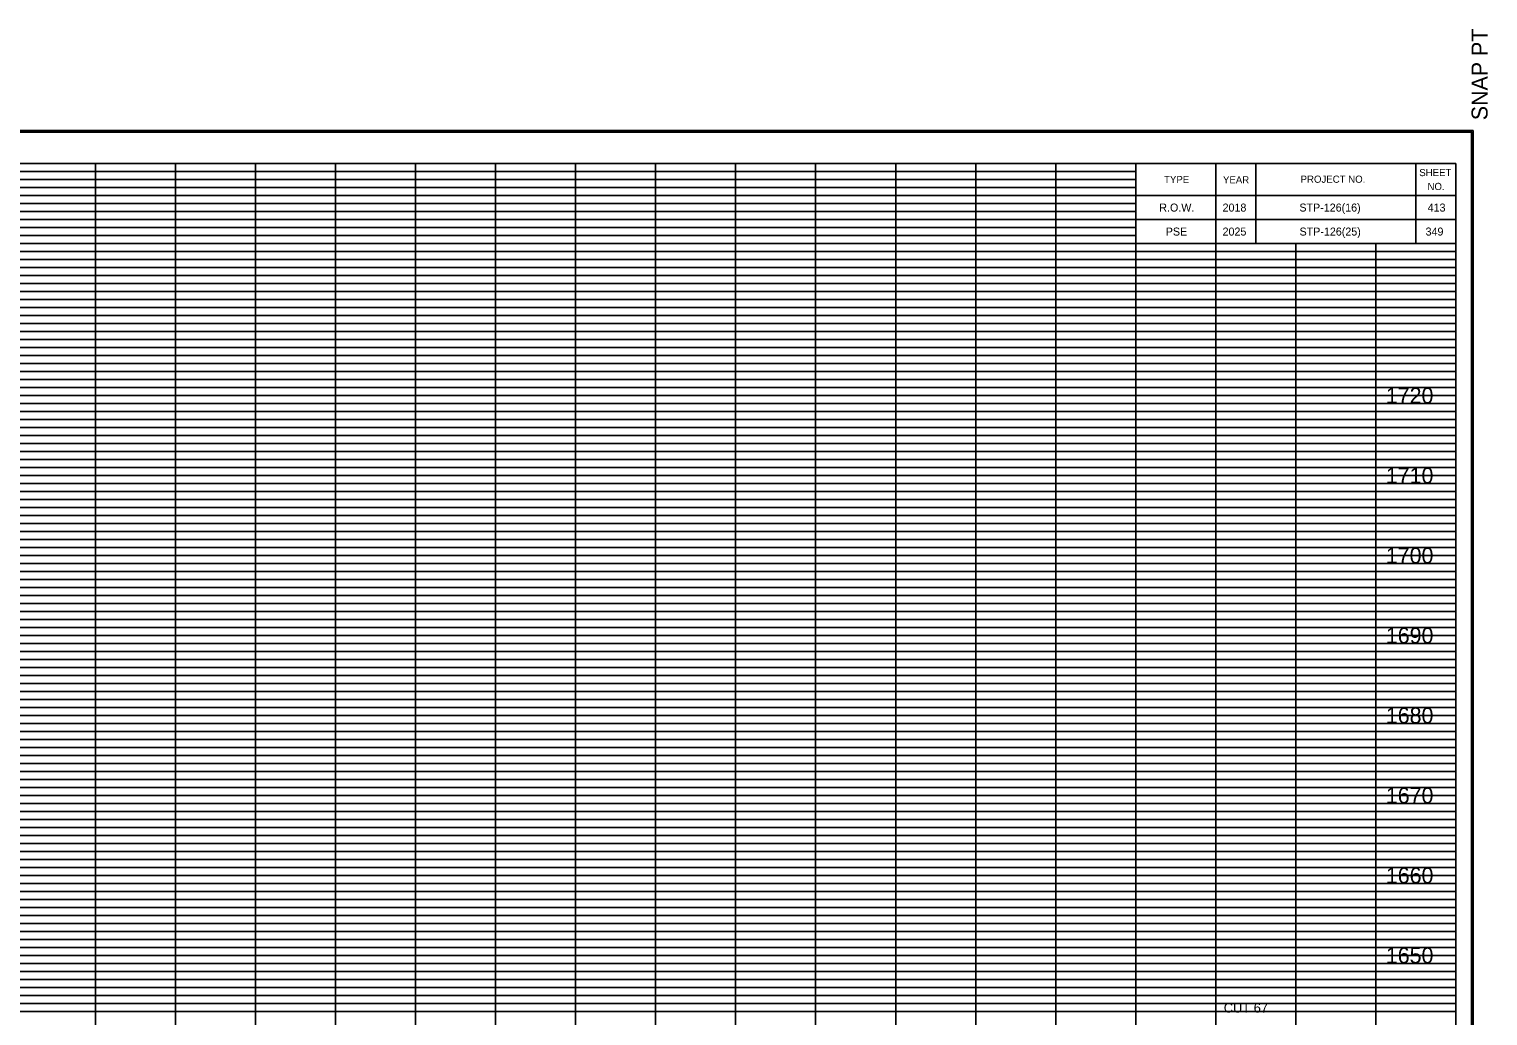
# Model space of a CAD drawing. Extents: x 980 to 1324, y 978 to 1497.
# Drawn here: x 1141.7 to 1324, y 1103.4 to 1226.8 of the extents above; entities that cross this region are included whole.
import ezdxf

# ---------------------------------------------------------------- set-up
doc = ezdxf.new("R2010")
doc.units = 0
for name, color, linetype in [('DESIGN - SCRATCH - User 1', 7, 'Continuous'), ('DESIGN - SHEET - Corner Text', 7, 'Continuous'), ('DESIGN - SHEET - Light Grid', 7, 'Continuous'), ('DESIGN - SHEET - Linework', 7, 'Continuous'), ('DESIGN - SHEET - Plot Shape', 7, 'Continuous'), ('DESIGN - TYPICAL - Finished Grade and Subgrade', 7, 'Continuous'), ('DESIGN - TYPICAL - Text', 7, 'Continuous')]:
    doc.layers.add(name, color=color, linetype=linetype)

# ---------------------------------------------------------------- blocks, each defined once
blk = doc.blocks.new('XSTSHT')
at = {"layer": 'DESIGN - SCRATCH - User 1'}
for p, q in [((28.5, 20.45), (28.5, 20.45)), ((29.24, 20.45), (29.24, 20.45)), ((30.49, 20.45), (30.49, 20.45)), ((31.74, 20.45), (31.74, 20.45)), ((28.5, 20.15), (28.5, 20.15)), ((29.24, 20.15), (29.24, 20.15)), ((30.49, 20.15), (30.49, 20.15)), ((31.74, 20.15), (31.74, 20.15))]:
    blk.add_line(p, q, dxfattribs=at)
at = {"layer": 'DESIGN - SHEET - Light Grid'}
for p, q in [((8, 20.9), (16, 20.9)), ((8, 20.8), (16, 20.8)), ((16, 20.9), (24, 20.9)), ((16, 20.8), (24, 20.8)), ((24, 20.9), (28, 20.9)), ((24, 20.8), (28, 20.8)), ((8, 20.7), (16, 20.7)), ((8, 20.6), (16, 20.6)), ((16, 20.7), (24, 20.7)), ((16, 20.6), (24, 20.6)), ((24, 20.7), (28, 20.7)), ((24, 20.6), (28, 20.6)), ((8, 20.5), (16, 20.5)), ((16, 20.5), (24, 20.5)), ((24, 20.5), (28, 20.5)), ((8, 20.4), (16, 20.4)), ((8, 20.3), (16, 20.3)), ((16, 20.4), (24, 20.4)), ((16, 20.3), (24, 20.3)), ((24, 20.4), (28, 20.4)), ((24, 20.3), (28, 20.3)), ((8, 20.2), (16, 20.2)), ((8, 20.1), (16, 20.1)), ((16, 20.2), (24, 20.2)), ((16, 20.1), (24, 20.1)), ((24, 20.2), (28, 20.2)), ((24, 20.1), (28, 20.1)), ((8, 19.9), (16, 19.9)), ((16, 19.9), (24, 19.9)), ((24, 19.9), (32, 19.9)), ((8, 19.8), (16, 19.8)), ((8, 19.7), (16, 19.7)), ((16, 19.8), (24, 19.8)), ((16, 19.7), (24, 19.7)), ((24, 19.8), (32, 19.8)), ((24, 19.7), (32, 19.7)), ((8, 19.6), (16, 19.6)), ((16, 19.6), (24, 19.6)), ((24, 19.6), (32, 19.6)), ((8, 19.5), (16, 19.5)), ((8, 19.4), (16, 19.4)), ((16, 19.5), (24, 19.5)), ((16, 19.4), (24, 19.4)), ((24, 19.5), (32, 19.5)), ((24, 19.4), (32, 19.4)), ((8, 19.3), (16, 19.3)), ((8, 19.2), (16, 19.2)), ((16, 19.3), (24, 19.3)), ((16, 19.2), (24, 19.2)), ((24, 19.3), (32, 19.3)), ((24, 19.2), (32, 19.2)), ((8, 19.1), (16, 19.1)), ((16, 19.1), (24, 19.1)), ((24, 19.1), (32, 19.1)), ((8, 18.9), (16, 18.9)), ((8, 18.8), (16, 18.8)), ((16, 18.9), (24, 18.9)), ((16, 18.8), (24, 18.8)), ((24, 18.9), (32, 18.9)), ((24, 18.8), (32, 18.8)), ((8, 18.7), (16, 18.7)), ((8, 18.6), (16, 18.6)), ((16, 18.7), (24, 18.7)), ((16, 18.6), (24, 18.6)), ((24, 18.7), (32, 18.7)), ((24, 18.6), (32, 18.6)), ((8, 18.5), (16, 18.5)), ((16, 18.5), (24, 18.5)), ((24, 18.5), (32, 18.5)), ((8, 18.4), (16, 18.4)), ((8, 18.3), (16, 18.3)), ((16, 18.4), (24, 18.4)), ((16, 18.3), (24, 18.3)), ((24, 18.4), (32, 18.4)), ((24, 18.3), (32, 18.3)), ((8, 18.2), (16, 18.2)), ((8, 18.1), (16, 18.1)), ((16, 18.2), (24, 18.2)), ((16, 18.1), (24, 18.1)), ((24, 18.2), (32, 18.2)), ((24, 18.1), (32, 18.1)), ((8, 17.9), (16, 17.9)), ((16, 17.9), (24, 17.9)), ((24, 17.9), (32, 17.9)), ((8, 17.8), (16, 17.8)), ((8, 17.7), (16, 17.7)), ((16, 17.8), (24, 17.8)), ((16, 17.7), (24, 17.7)), ((24, 17.8), (32, 17.8)), ((24, 17.7), (32, 17.7)), ((8, 17.6), (16, 17.6)), ((8, 17.5), (16, 17.5)), ((16, 17.6), (24, 17.6)), ((16, 17.5), (24, 17.5)), ((24, 17.6), (32, 17.6)), ((24, 17.5), (32, 17.5)), ((8, 17.4), (16, 17.4)), ((16, 17.4), (24, 17.4)), ((24, 17.4), (32, 17.4)), ((8, 17.3), (16, 17.3)), ((8, 17.2), (16, 17.2)), ((16, 17.3), (24, 17.3)), ((16, 17.2), (24, 17.2)), ((24, 17.3), (32, 17.3)), ((24, 17.2), (32, 17.2)), ((8, 17.1), (16, 17.1)), ((16, 17.1), (24, 17.1)), ((24, 17.1), (32, 17.1)), ((8, 16.9), (16, 16.9)), ((8, 16.8), (16, 16.8)), ((16, 16.9), (24, 16.9)), ((16, 16.8), (24, 16.8)), ((24, 16.9), (32, 16.9)), ((24, 16.8), (32, 16.8)), ((8, 16.7), (16, 16.7)), ((8, 16.6), (16, 16.6)), ((16, 16.7), (24, 16.7)), ((16, 16.6), (24, 16.6)), ((24, 16.7), (32, 16.7)), ((24, 16.6), (32, 16.6)), ((8, 16.5), (16, 16.5)), ((16, 16.5), (24, 16.5)), ((24, 16.5), (32, 16.5)), ((8, 16.4), (16, 16.4)), ((8, 16.3), (16, 16.3)), ((16, 16.4), (24, 16.4)), ((16, 16.3), (24, 16.3)), ((24, 16.4), (32, 16.4)), ((24, 16.3), (32, 16.3)), ((8, 16.2), (16, 16.2)), ((8, 16.1), (16, 16.1)), ((16, 16.2), (24, 16.2)), ((16, 16.1), (24, 16.1)), ((24, 16.2), (32, 16.2)), ((24, 16.1), (32, 16.1)), ((8, 15.9), (16, 15.9)), ((16, 15.9), (24, 15.9)), ((24, 15.9), (32, 15.9)), ((8, 15.8), (16, 15.8)), ((8, 15.7), (16, 15.7)), ((16, 15.8), (24, 15.8)), ((16, 15.7), (24, 15.7)), ((24, 15.8), (32, 15.8)), ((24, 15.7), (32, 15.7)), ((8, 15.6), (16, 15.6)), ((8, 15.5), (16, 15.5)), ((16, 15.6), (24, 15.6)), ((16, 15.5), (24, 15.5)), ((24, 15.6), (32, 15.6)), ((24, 15.5), (32, 15.5)), ((8, 15.4), (16, 15.4)), ((16, 15.4), (24, 15.4)), ((24, 15.4), (32, 15.4)), ((8, 15.3), (16, 15.3)), ((8, 15.2), (16, 15.2)), ((16, 15.3), (24, 15.3)), ((16, 15.2), (24, 15.2)), ((24, 15.3), (32, 15.3)), ((24, 15.2), (32, 15.2)), ((8, 15.1), (16, 15.1)), ((16, 15.1), (24, 15.1)), ((24, 15.1), (32, 15.1)), ((8, 14.9), (16, 14.9)), ((8, 14.8), (16, 14.8)), ((16, 14.9), (24, 14.9)), ((16, 14.8), (24, 14.8)), ((24, 14.9), (32, 14.9)), ((24, 14.8), (32, 14.8)), ((8, 14.7), (16, 14.7)), ((8, 14.6), (16, 14.6)), ((16, 14.7), (24, 14.7)), ((16, 14.6), (24, 14.6)), ((24, 14.7), (32, 14.7)), ((24, 14.6), (32, 14.6)), ((8, 14.5), (16, 14.5)), ((16, 14.5), (24, 14.5)), ((24, 14.5), (32, 14.5)), ((8, 14.4), (16, 14.4)), ((8, 14.3), (16, 14.3)), ((16, 14.4), (24, 14.4)), ((16, 14.3), (24, 14.3)), ((24, 14.4), (32, 14.4)), ((24, 14.3), (32, 14.3)), ((8, 14.2), (16, 14.2)), ((8, 14.1), (16, 14.1)), ((16, 14.2), (24, 14.2)), ((16, 14.1), (24, 14.1)), ((24, 14.2), (32, 14.2)), ((24, 14.1), (32, 14.1)), ((8, 13.9), (16, 13.9)), ((16, 13.9), (24, 13.9)), ((24, 13.9), (32, 13.9)), ((8, 13.8), (16, 13.8)), ((8, 13.7), (16, 13.7)), ((16, 13.8), (24, 13.8)), ((16, 13.7), (24, 13.7)), ((24, 13.8), (32, 13.8)), ((24, 13.7), (32, 13.7)), ((8, 13.6), (16, 13.6)), ((8, 13.5), (16, 13.5)), ((16, 13.6), (24, 13.6)), ((16, 13.5), (24, 13.5)), ((24, 13.6), (32, 13.6)), ((24, 13.5), (32, 13.5)), ((8, 13.4), (16, 13.4)), ((16, 13.4), (24, 13.4)), ((24, 13.4), (32, 13.4)), ((8, 13.3), (16, 13.3)), ((8, 13.2), (16, 13.2)), ((16, 13.3), (24, 13.3)), ((16, 13.2), (24, 13.2)), ((24, 13.3), (32, 13.3)), ((24, 13.2), (32, 13.2)), ((8, 13.1), (16, 13.1)), ((16, 13.1), (24, 13.1)), ((24, 13.1), (32, 13.1)), ((8, 12.9), (16, 12.9)), ((8, 12.8), (16, 12.8)), ((16, 12.9), (24, 12.9)), ((16, 12.8), (24, 12.8)), ((24, 12.9), (32, 12.9)), ((24, 12.8), (32, 12.8)), ((8, 12.7), (16, 12.7)), ((8, 12.6), (16, 12.6)), ((16, 12.7), (24, 12.7)), ((16, 12.6), (24, 12.6)), ((24, 12.7), (32, 12.7)), ((24, 12.6), (32, 12.6)), ((8, 12.5), (16, 12.5)), ((8, 12.4), (16, 12.4)), ((16, 12.5), (24, 12.5)), ((16, 12.4), (24, 12.4)), ((24, 12.5), (32, 12.5)), ((24, 12.4), (32, 12.4)), ((8, 12.3), (16, 12.3)), ((16, 12.3), (24, 12.3)), ((24, 12.3), (32, 12.3)), ((8, 12.2), (16, 12.2)), ((8, 12.1), (16, 12.1)), ((16, 12.2), (24, 12.2)), ((16, 12.1), (24, 12.1)), ((24, 12.2), (32, 12.2)), ((24, 12.1), (32, 12.1)), ((8, 11.9), (16, 11.9)), ((16, 11.9), (24, 11.9)), ((24, 11.9), (32, 11.9)), ((8, 11.8), (16, 11.8)), ((8, 11.7), (16, 11.7)), ((16, 11.8), (24, 11.8)), ((16, 11.7), (24, 11.7)), ((24, 11.8), (32, 11.8)), ((24, 11.7), (32, 11.7)), ((8, 11.6), (16, 11.6)), ((8, 11.5), (16, 11.5)), ((16, 11.6), (24, 11.6)), ((16, 11.5), (24, 11.5)), ((24, 11.6), (32, 11.6)), ((24, 11.5), (32, 11.5)), ((8, 11.4), (16, 11.4)), ((16, 11.4), (24, 11.4)), ((24, 11.4), (32, 11.4)), ((8, 11.3), (16, 11.3)), ((8, 11.2), (16, 11.2)), ((16, 11.3), (24, 11.3)), ((16, 11.2), (24, 11.2)), ((24, 11.3), (32, 11.3)), ((24, 11.2), (32, 11.2)), ((8, 11.1), (16, 11.1)), ((16, 11.1), (24, 11.1)), ((24, 11.1), (32, 11.1)), ((8, 10.9), (16, 10.9)), ((8, 10.8), (16, 10.8)), ((16, 10.9), (24, 10.9)), ((16, 10.8), (24, 10.8)), ((24, 10.9), (32, 10.9)), ((24, 10.8), (32, 10.8)), ((8, 10.7), (16, 10.7)), ((8, 10.6), (16, 10.6)), ((16, 10.7), (24, 10.7)), ((16, 10.6), (24, 10.6)), ((24, 10.7), (32, 10.7)), ((24, 10.6), (32, 10.6)), ((8, 10.5), (16, 10.5)), ((8, 10.4), (16, 10.4)), ((16, 10.5), (24, 10.5)), ((16, 10.4), (24, 10.4)), ((24, 10.5), (32, 10.5)), ((24, 10.4), (32, 10.4))]:
    blk.add_line(p, q, dxfattribs=at)
at = {"layer": 'DESIGN - SHEET - Linework'}
for p, q in [((-1.823, 21.414), (32.217, 21.414)), ((32.217, 21.414), (32.217, -0.414)), ((15, 0), (15, 21)), ((16, 0), (16, 21)), ((17, 0), (17, 21)), ((18, 0), (18, 21)), ((19, 0), (19, 21)), ((20, 0), (20, 21)), ((21, 0), (21, 21)), ((22, 0), (22, 21)), ((23, 0), (23, 21)), ((24, 0), (24, 21)), ((25, 0), (25, 21)), ((26, 0), (26, 21)), ((27, 0), (27, 21)), ((0, 20), (28, 20)), ((28, 0), (28, 20)), ((29, 0), (29, 20)), ((30, 0), (30, 20)), ((31, 0), (31, 20)), ((0, 19), (32, 19)), ((0, 18), (32, 18)), ((0, 17), (32, 17)), ((0, 16), (32, 16)), ((0, 15), (32, 15)), ((0, 14), (32, 14)), ((0, 13), (32, 13)), ((0, 12), (32, 12)), ((0, 11), (32, 11))]:
    blk.add_line(p, q, dxfattribs=at)
for points in [[(0, 21), (0, 0), (32, 0), (32, 21), (0, 21)], [(28, 21), (28, 20), (32, 20), (32, 21), (31.5, 21), (31.5, 20), (29.5, 20), (29.5, 21), (29, 21), (29, 20), (32, 20), (28, 20), (28, 20.3), (32, 20.3), (32, 20.6), (28, 20.6)]]:
    blk.add_lwpolyline(points, dxfattribs=at)
at = {"layer": 'DESIGN - SHEET - Plot Shape'}
for points in [[(-1.803, 21.394), (32.197, 21.394), (32.197, -0.394), (-1.803, -0.394)], [(-0.85, 21), (32, 21), (32, -0.25), (-0.85, -0.25)]]:
    blk.add_lwpolyline(points, close=True, dxfattribs=at)
at = {"layer": 'DESIGN - SHEET - Corner Text'}
blk.add_text('  SNAP PT', height=0.2, rotation=90, dxfattribs=at).set_placement((32.397, 21.394))
for s, p in [('TYPE', (28.354, 20.756)), ('YEAR', (29.09, 20.752)), ('PROJECT NO.', (30.06, 20.76)), ('SHEET', (31.543, 20.843)), ('NO.', (31.646, 20.669))]:
    blk.add_text(s, height=0.09, dxfattribs=at).set_placement(p)

msp = doc.modelspace()

# ---------------------------------------------------------------- linework, layer by layer
at = {"layer": 'DESIGN - SHEET - Plot Shape'}
msp.add_lwpolyline([(991.5, 997.5), (1320, 997.5), (1320, 1210), (991.5, 1210)], close=True, dxfattribs=at)

# ---------------------------------------------------------------- block references
at = {"layer": 'DESIGN - TYPICAL - Finished Grade and Subgrade', "xscale": 10, "yscale": 10}
msp.add_blockref('XSTSHT', (1000, 1000), dxfattribs=at)

# ---------------------------------------------------------------- texts
at = {"layer": 'DESIGN - SHEET - Corner Text'}
for s, height, p in [('R.O.W.', 1, (1282.94, 1204)), ('2018', 1, (1290.85, 1204)), ('STP-126(16)', 1, (1300.45, 1204)), ('413', 1, (1316.48, 1204)), ('PSE', 1, (1283.75, 1201)), ('2025', 1, (1290.85, 1201)), ('STP-126(25)', 1, (1300.47, 1201)), ('349', 1, (1316.22, 1201)), ('1720', 2, (1311.25, 1180)), ('1710', 2, (1311.25, 1170)), ('1700', 2, (1311.25, 1160)), ('1690', 2, (1311.25, 1150)), ('1680', 2, (1311.25, 1140)), ('1670', 2, (1311.25, 1130)), ('1660', 2, (1311.25, 1120)), ('1650', 2, (1311.25, 1110))]:
    msp.add_text(s, height=height, dxfattribs=at).set_placement(p)
at = {"layer": 'DESIGN - TYPICAL - Text'}
msp.add_text('CUT 67', height=1.2, dxfattribs=at).set_placement((1291, 1103.84))

doc.saveas('drawing.dxf')
